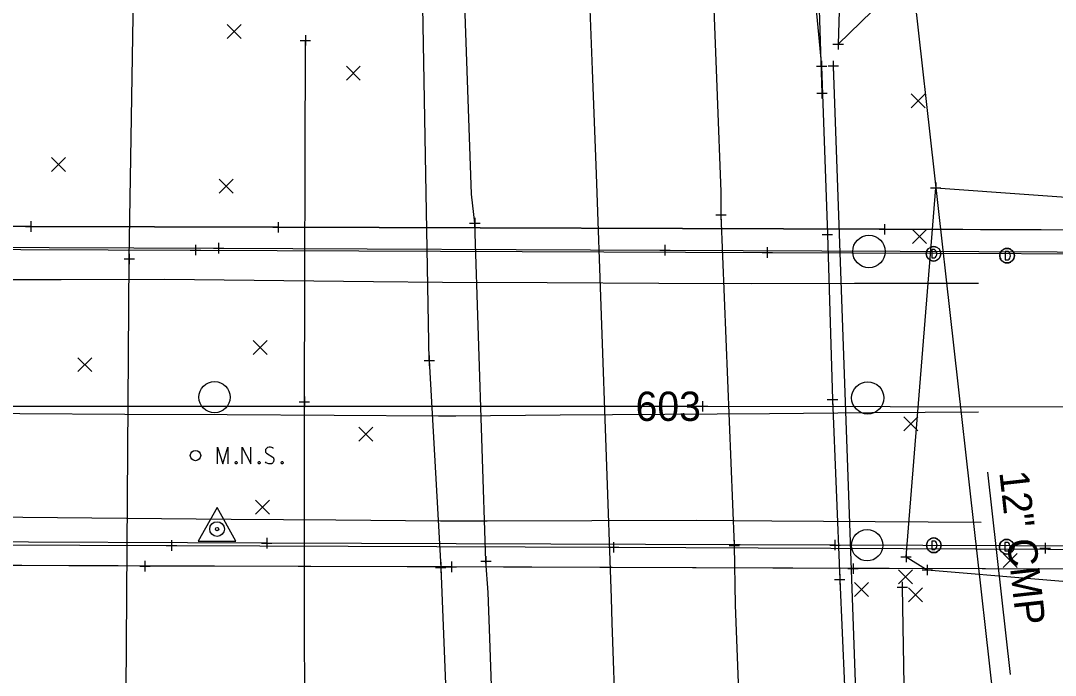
# Model space of a CAD drawing. Extents: x 146022 to 147632, y 437624 to 440659.
# Drawn here: x 146968.6 to 147067.5, y 438601.8 to 438664.4 of the extents above; entities that cross this region are included whole.
import ezdxf

# ---------------------------------------------------------------- set-up
doc = ezdxf.new("R2010")
doc.units = 0
for name, color, linetype in [('_CIVIL_CONSTRUCTION', 7, 'Continuous'), ('BR_X_SV_Bottom_of_Beam', 7, 'Continuous'), ('BR_X_SV_Pier', 7, 'Continuous'), ('Default', 7, 'Continuous'), ('DR_Channel', 7, 'Continuous'), ('DR_P_Paved_Gutter', 7, 'Continuous'), ('DR_P_Underdrain', 7, 'Continuous'), ('DR_X_Cells', 7, 'Continuous'), ('DR_X_Storm_Sewer', 7, 'Continuous'), ('DR_X_Text', 7, 'Continuous'), ('DT_X_Triangles', 7, 'Continuous'), ('GE_P_Alignment_100_Cardinal_Points', 7, 'Continuous'), ('GE_P_Alignment_100_Stations', 7, 'Continuous'), ('PF_X_Ground_Line', 7, 'Continuous'), ('PV_P_Curb', 7, 'Continuous'), ('PV_P_Joint', 7, 'Continuous'), ('RD_P_Anchor_Assembly', 7, 'Continuous'), ('RD_P_Fence', 7, 'Continuous'), ('RD_P_GR_Lt_Replaced', 7, 'Continuous'), ('RW_P_Const_Limits', 7, 'Continuous'), ('SC_Scratch3', 7, 'Continuous'), ('SH_Text', 7, 'Continuous'), ('SV_X_Terrain_Boundary', 7, 'Continuous'), ('UT_X_Electric', 7, 'Continuous')]:
    doc.layers.add(name, color=color, linetype=linetype)

msp = doc.modelspace()

# ---------------------------------------------------------------- linework, layer by layer
at = {"layer": '_CIVIL_CONSTRUCTION'}
for p, q in [((146988.311, 438662.735), (146989.644, 438664.07)), ((146988.311, 438664.07), (146989.644, 438662.735)), ((146999.698, 438658.743), (147001.031, 438660.078)), ((146999.698, 438660.078), (147001.031, 438658.743)), ((147053.702, 438656.103), (147055.036, 438657.438)), ((147053.702, 438657.438), (147055.036, 438656.103)), ((146971.505, 438650.019), (146972.838, 438651.354)), ((146971.505, 438651.354), (146972.838, 438650.019)), ((146987.528, 438647.937), (146988.861, 438649.272)), ((146987.528, 438649.272), (146988.861, 438647.937)), ((147053.825, 438643.128), (147055.158, 438644.463)), ((147053.825, 438644.463), (147055.158, 438643.128)), ((146990.785, 438632.502), (146992.118, 438633.837)), ((146990.785, 438633.837), (146992.118, 438632.502)), ((146974.032, 438630.864), (146975.365, 438632.199)), ((146974.032, 438632.199), (146975.365, 438630.864)), ((147052.986, 438625.203), (147054.319, 438626.538)), ((147052.986, 438626.538), (147054.319, 438625.203)), ((147000.881, 438624.21), (147002.214, 438625.545)), ((147000.881, 438625.545), (147002.214, 438624.21)), ((146991.024, 438617.231), (146992.357, 438618.566)), ((146991.024, 438618.566), (146992.357, 438617.231)), ((147062.501, 438612.127), (147063.834, 438613.462)), ((147062.501, 438613.462), (147063.834, 438612.127)), ((147052.474, 438610.572), (147053.807, 438611.907)), ((147052.474, 438611.907), (147053.807, 438610.572)), ((147048.271, 438609.372), (147049.605, 438610.707)), ((147048.271, 438610.707), (147049.605, 438609.372)), ((147053.453, 438608.838), (147054.787, 438610.173)), ((147053.453, 438610.173), (147054.787, 438608.838))]:
    msp.add_line(p, q, dxfattribs=at)
at = {"layer": 'BR_X_SV_Bottom_of_Beam'}
for points in [[(146915.587, 438639.808), (146925.317, 438639.819), (146934.821, 438639.83), (146945.2, 438639.842), (146955.198, 438639.747), (146962.426, 438639.678), (146972.429, 438639.685), (146982.304, 438639.693), (147002.305, 438639.484), (147008.894, 438639.416), (147018.894, 438639.375), (147029.574, 438639.335), (147038.394, 438639.296), (147048.275, 438639.31), (147058.405, 438639.324), (147060.13, 438639.326)], [(147060.147, 438626.995), (147049.92, 438626.917), (147040.15, 438626.842), (147030.152, 438626.766), (147020.152, 438626.69), (147010.154, 438626.614), (147008.517, 438626.602), (146998.516, 438626.658), (146988.288, 438626.717), (146978.515, 438626.772), (146968.486, 438626.829), (146964.186, 438626.853), (146953.877, 438626.667), (146944.082, 438626.48), (146934.171, 438626.293), (146931.304, 438626.257), (146922.277, 438626.712), (146912.643, 438627.012)], [(147060.393, 438616.42), (147050.239, 438616.494), (147040.369, 438616.566), (147033.157, 438616.619), (147023.159, 438616.592), (147013.16, 438616.565), (147008.681, 438616.553), (146998.682, 438616.645), (146988.669, 438616.737), (146978.685, 438616.83), (146968.751, 438616.922), (146966.697, 438616.94), (146956.246, 438616.918), (146946.661, 438616.897), (146936.054, 438616.876), (146930.378, 438616.865), (146921.088, 438616.438), (146911.185, 438616.183)]]:
    msp.add_lwpolyline(points, dxfattribs=at)
at = {"layer": 'BR_X_SV_Pier'}
for centre, radius in [((147049.66, 438642.354), 1.554), ((146987.091, 438628.418), 1.492), ((147049.538, 438628.346), 1.535), ((147049.487, 438614.263), 1.503)]:
    msp.add_circle(centre, radius, dxfattribs=at)
at = {"layer": 'DR_Channel'}
for points in [[(147043.412, 438708.595), (147044.478, 438678.513), (147045.162, 438657.493)], [(146993.311, 438472.759), (146995.719, 438578.194), (146995.684, 438627.981), (146995.782, 438662.545)]]:
    msp.add_lwpolyline(points, dxfattribs=at)
at = {"layer": 'DR_P_Paved_Gutter'}
msp.add_lwpolyline([(146978.603, 438595.669), (146978.94, 438641.642), (146979.937, 438703.502), (146984.388, 438761.316), (146986.686, 438784.307)], dxfattribs=at)
at = {"layer": 'DR_P_Underdrain'}
msp.add_lwpolyline([(147046.249, 438660.096), (147048.499, 438596.716)], dxfattribs=at)
at = {"layer": 'DR_X_Cells'}
for points in [[(147053.205, 438613.153), (147056.046, 438648.453), (147083.169, 438646.508), (147085.148, 438646.666)], [(147053.205, 438613.153), (147055.234, 438611.895), (147087.267, 438609.219), (147085.148, 438646.666)]]:
    msp.add_lwpolyline(points, dxfattribs=at)
at = {"layer": 'DR_X_Storm_Sewer'}
msp.add_line((147053.412, 438671.931), (147066.551, 438554.767), dxfattribs=at)
at = {"layer": 'DR_X_Text'}
msp.add_line((147063.177, 438601.899), (147061.008, 438621.247), dxfattribs=at)
at = {"layer": 'DT_X_Triangles'}
for p, q in [((147055.837, 438642.139), (147055.837, 438642.139)), ((147055.837, 438642.139), (147055.837, 438642.139)), ((147055.837, 438642.139), (147055.837, 438642.139)), ((147055.837, 438642.139), (147055.837, 438642.139)), ((147055.837, 438642.139), (147055.837, 438642.139)), ((147062.858, 438641.955), (147062.858, 438641.955)), ((147062.858, 438641.955), (147062.858, 438641.955)), ((147062.858, 438641.955), (147062.858, 438641.955)), ((147062.858, 438641.955), (147062.858, 438641.955)), ((147062.858, 438641.955), (147062.858, 438641.955)), ((147055.857, 438614.257), (147055.857, 438614.257)), ((147055.857, 438614.257), (147055.857, 438614.257)), ((147055.857, 438614.257), (147055.857, 438614.257)), ((147055.857, 438614.257), (147055.857, 438614.257)), ((147055.857, 438614.257), (147055.857, 438614.257)), ((147062.827, 438614.123), (147062.827, 438614.123)), ((147062.827, 438614.123), (147062.827, 438614.123)), ((147062.827, 438614.123), (147062.827, 438614.123)), ((147062.827, 438614.123), (147062.827, 438614.123)), ((147062.827, 438614.123), (147062.827, 438614.123))]:
    msp.add_line(p, q, dxfattribs=at)
for centre in [(147055.837, 438642.139), (147062.858, 438641.955), (147055.857, 438614.257), (147062.827, 438614.123)]:
    msp.add_circle(centre, 0.7, dxfattribs=at)
at = {"layer": 'GE_P_Alignment_100_Cardinal_Points'}
for points in [[(146886.697, 438643.146), (146914.629, 438642.971), (146987.485, 438642.673), (147030.154, 438642.484), (147082.653, 438642.27), (147087.676, 438642.282), (147088.142, 438642.428), (147088.538, 438642.44)], [(146886.273, 438614.58), (146893.974, 438614.564), (146939.097, 438614.385), (146982.973, 438614.237), (147025.25, 438614.063), (147087.547, 438613.803), (147088.31, 438613.791)]]:
    msp.add_lwpolyline(points, dxfattribs=at)
at = {"layer": 'GE_P_Alignment_100_Stations'}
for points in [[(146886.617, 438645.057), (146916.632, 438644.953), (146969.533, 438644.744), (146993.171, 438644.674), (147051.149, 438644.479), (147087.815, 438644.354), (147088.055, 438644.306), (147088.543, 438644.321)], [(147088.417, 438611.938), (147085.161, 438611.927), (147048.137, 438612.028), (147009.735, 438612.191), (146980.437, 438612.254), (146944.113, 438612.41), (146906.055, 438612.508), (146890.588, 438612.592), (146885.707, 438612.644)]]:
    msp.add_lwpolyline(points, dxfattribs=at)
at = {"layer": 'PF_X_Ground_Line'}
msp.add_lwpolyline([(147031.265, 439100.493), (147033.124, 439049.689), (147035.536, 438989.571), (147036.948, 438926.083), (147039.28, 438864.722), (147041.137, 438801.73), (147042.54, 438743.359), (147043.212, 438709.888), (147047.269, 438680.177), (147046.71, 438662.178), (147051.053, 438666.422), (147056.824, 438665.984), (147058.213, 438672.792), (147056.903, 438679.132), (147056.31, 438685.267)], dxfattribs=at)
at = {"layer": 'PV_P_Curb'}
msp.add_line((147025.042, 438609.21), (147023.6, 438649.734), dxfattribs=at)
for points in [[(147023.6, 438649.734), (147023.222, 438659.727), (147022.845, 438669.72), (147022.467, 438679.713), (147022.09, 438689.706), (147021.712, 438699.699), (147021.334, 438709.691), (147020.957, 438719.684), (147020.579, 438729.677), (147020.202, 438739.67), (147019.824, 438749.663), (147019.447, 438759.656), (147019.069, 438769.649), (147018.692, 438779.642), (147018.314, 438789.634), (147017.936, 438799.627), (147017.559, 438809.62), (147017.181, 438819.613), (147016.804, 438829.606), (147016.426, 438839.599), (147016.049, 438849.592), (147015.671, 438859.584)], [(146887.294, 438628.027), (146961.353, 438627.571), (147033.742, 438627.551), (147087.577, 438627.48)], [(147030.271, 438456.925), (147029.928, 438466.919), (147029.584, 438476.913), (147029.241, 438486.907), (147028.898, 438496.901), (147028.555, 438506.896), (147028.212, 438516.89), (147027.869, 438526.884), (147027.525, 438536.878), (147027.182, 438546.872), (147026.839, 438556.866), (147026.496, 438566.86), (147026.153, 438576.854), (147025.809, 438586.848), (147025.466, 438596.843), (147025.123, 438606.837), (147025.042, 438609.21)]]:
    msp.add_lwpolyline(points, dxfattribs=at)
at = {"layer": 'PV_P_Joint'}
msp.add_lwpolyline([(146985.529, 438614.654), (146989.129, 438614.654), (146987.329, 438617.874)], close=True, dxfattribs=at)
for radius in [0.7, 0.16]:
    msp.add_circle((146987.329, 438615.81), radius, dxfattribs=at)
at = {"layer": 'RD_P_Anchor_Assembly'}
for p, q in [((146995.282, 438662.545), (146996.282, 438662.545)), ((146995.782, 438663.045), (146995.782, 438662.045)), ((146995.782, 438662.545), (146995.782, 438662.545)), ((147046.71, 438662.678), (147046.71, 438661.678)), ((147046.21, 438662.178), (147047.21, 438662.178)), ((147046.71, 438662.178), (147046.71, 438662.178)), ((147045.134, 438660.585), (147045.134, 438659.585)), ((147046.249, 438660.596), (147046.249, 438659.596)), ((147044.634, 438660.085), (147045.634, 438660.085)), ((147045.134, 438660.085), (147045.134, 438660.085)), ((147045.749, 438660.096), (147046.749, 438660.096)), ((147046.249, 438660.096), (147046.249, 438660.096)), ((147044.662, 438657.493), (147045.662, 438657.493)), ((147045.162, 438657.993), (147045.162, 438656.993)), ((147045.162, 438657.493), (147045.162, 438657.493)), ((147055.546, 438648.453), (147056.546, 438648.453)), ((147056.046, 438648.953), (147056.046, 438647.953)), ((147056.046, 438648.453), (147056.046, 438648.453)), ((147011.976, 438645.558), (147011.976, 438644.558)), ((147035.004, 438645.875), (147036.004, 438645.875)), ((147035.504, 438646.375), (147035.504, 438645.375)), ((147035.504, 438645.875), (147035.504, 438645.875)), ((146969.033, 438644.744), (146970.033, 438644.744)), ((146969.533, 438645.244), (146969.533, 438644.244)), ((146969.533, 438644.744), (146969.533, 438644.744)), ((146992.671, 438644.674), (146993.671, 438644.674)), ((146993.171, 438645.174), (146993.171, 438644.174)), ((146993.171, 438644.674), (146993.171, 438644.674)), ((147011.476, 438645.058), (147012.476, 438645.058)), ((147011.976, 438645.058), (147011.976, 438645.058)), ((147045.684, 438644.484), (147045.684, 438643.484)), ((147050.649, 438644.479), (147051.649, 438644.479)), ((147051.149, 438644.979), (147051.149, 438643.979)), ((147051.149, 438644.479), (147051.149, 438644.479)), ((147045.184, 438643.984), (147046.184, 438643.984)), ((147045.684, 438643.984), (147045.684, 438643.984)), ((146984.777, 438642.496), (146985.777, 438642.496)), ((146985.277, 438642.996), (146985.277, 438641.996)), ((146985.277, 438642.496), (146985.277, 438642.496)), ((146986.985, 438642.673), (146987.985, 438642.673)), ((146987.485, 438643.173), (146987.485, 438642.173)), ((146987.485, 438642.673), (146987.485, 438642.673)), ((147029.654, 438642.484), (147030.654, 438642.484)), ((147030.154, 438642.984), (147030.154, 438641.984)), ((147030.154, 438642.484), (147030.154, 438642.484)), ((147039.933, 438642.754), (147039.933, 438641.754)), ((146978.44, 438641.642), (146979.44, 438641.642)), ((146978.94, 438642.142), (146978.94, 438641.142)), ((146978.94, 438641.642), (146978.94, 438641.642)), ((147039.433, 438642.254), (147040.433, 438642.254)), ((147039.933, 438642.254), (147039.933, 438642.254)), ((147007.124, 438631.915), (147008.124, 438631.915)), ((147007.624, 438632.415), (147007.624, 438631.415)), ((147007.624, 438631.915), (147007.624, 438631.915)), ((147046.174, 438628.711), (147046.174, 438627.711)), ((146995.184, 438627.981), (146996.184, 438627.981)), ((146995.684, 438628.481), (146995.684, 438627.481)), ((146995.684, 438627.981), (146995.684, 438627.981)), ((147033.742, 438628.051), (147033.742, 438627.051)), ((147045.674, 438628.211), (147046.674, 438628.211)), ((147046.174, 438628.211), (147046.174, 438628.211)), ((147033.242, 438627.551), (147034.242, 438627.551)), ((147033.742, 438627.551), (147033.742, 438627.551)), ((146982.973, 438614.737), (146982.973, 438613.737)), ((146992.08, 438614.964), (146992.08, 438613.964)), ((147036.778, 438614.744), (147036.778, 438613.744)), ((147046.407, 438614.779), (147046.407, 438613.779)), ((146982.473, 438614.237), (146983.473, 438614.237)), ((146982.973, 438614.237), (146982.973, 438614.237)), ((146991.58, 438614.464), (146992.58, 438614.464)), ((146992.08, 438614.464), (146992.08, 438614.464)), ((147024.75, 438614.063), (147025.75, 438614.063)), ((147025.25, 438614.563), (147025.25, 438613.563)), ((147025.25, 438614.063), (147025.25, 438614.063)), ((147036.278, 438614.244), (147037.278, 438614.244)), ((147036.778, 438614.244), (147036.778, 438614.244)), ((147045.907, 438614.279), (147046.907, 438614.279)), ((147046.407, 438614.279), (147046.407, 438614.279)), ((147066.008, 438613.978), (147067.008, 438613.978)), ((147066.508, 438614.478), (147066.508, 438613.478)), ((147066.508, 438613.978), (147066.508, 438613.978)), ((146980.437, 438612.754), (146980.437, 438611.754)), ((147013.041, 438613.231), (147013.041, 438612.231)), ((147052.705, 438613.153), (147053.705, 438613.153)), ((147053.205, 438613.653), (147053.205, 438612.653)), ((147053.205, 438613.153), (147053.205, 438613.153)), ((146979.937, 438612.254), (146980.937, 438612.254)), ((146980.437, 438612.254), (146980.437, 438612.254)), ((147008.213, 438612.13), (147009.213, 438612.13)), ((147008.713, 438612.63), (147008.713, 438611.63)), ((147008.713, 438612.13), (147008.713, 438612.13)), ((147009.235, 438612.191), (147010.235, 438612.191)), ((147009.735, 438612.691), (147009.735, 438611.691)), ((147009.735, 438612.191), (147009.735, 438612.191)), ((147012.541, 438612.731), (147013.541, 438612.731)), ((147013.041, 438612.731), (147013.041, 438612.731)), ((147047.637, 438612.028), (147048.637, 438612.028)), ((147048.137, 438612.528), (147048.137, 438611.528)), ((147048.137, 438612.028), (147048.137, 438612.028)), ((147054.734, 438611.895), (147055.734, 438611.895)), ((147055.234, 438612.395), (147055.234, 438611.395)), ((147055.234, 438611.895), (147055.234, 438611.895)), ((147046.368, 438610.995), (147047.368, 438610.995)), ((147046.868, 438611.495), (147046.868, 438610.495)), ((147046.868, 438610.995), (147046.868, 438610.995)), ((147052.345, 438610.265), (147053.345, 438610.265)), ((147052.845, 438610.765), (147052.845, 438609.765)), ((147052.845, 438610.265), (147052.845, 438610.265))]:
    msp.add_line(p, q, dxfattribs=at)
at = {"layer": 'RD_P_Fence'}
msp.add_lwpolyline([(147052.845, 438610.265), (147053.024, 438598.999), (147056.407, 438577.47), (147060.095, 438566.361), (147063.255, 438556.856), (147064.735, 438553.438)], dxfattribs=at)
at = {"layer": 'RD_P_GR_Lt_Replaced'}
for points in [[(147007.624, 438631.915), (147006.832, 438674.725), (147005.435, 438733.475), (147003.268, 438784.298), (147000.579, 438849.422), (146998.523, 438912.12), (146996.336, 438976.527), (146994.653, 439039.1), (146992.525, 439098.481), (146992.611, 439099.809)], [(147028.78, 439100.289), (147030.702, 439050.099), (147032.83, 438989.568), (147034.209, 438926.711), (147035.765, 438865.146), (147038.939, 438801.428), (147040.729, 438744.008), (147041.91, 438709.752), (147043.365, 438678.613), (147045.134, 438660.085), (147045.684, 438643.984), (147046.174, 438628.211), (147046.868, 438610.995), (147047.321, 438600.784)], [(147007.624, 438631.915), (147008.713, 438612.13), (147011.847, 438534.062)]]:
    msp.add_lwpolyline(points, dxfattribs=at)
at = {"layer": 'RW_P_Const_Limits'}
for points in [[(146987.363, 438622.04), (146987.363, 438623.64), (146987.87, 438622.04), (146988.355, 438623.64), (146988.355, 438622.04)], [(146989.733, 438622.04), (146989.733, 438623.64), (146990.56, 438622.04), (146990.56, 438623.64)], [(146992.709, 438623.527), (146992.687, 438623.552), (146992.654, 438623.577), (146992.555, 438623.615), (146992.434, 438623.64), (146992.345, 438623.64), (146992.312, 438623.64), (146992.169, 438623.602), (146992.048, 438623.527), (146991.971, 438623.426), (146991.949, 438623.325), (146991.949, 438623.249), (146991.971, 438623.149), (146992.059, 438623.061), (146992.665, 438622.683), (146992.72, 438622.632), (146992.742, 438622.582), (146992.764, 438622.506), (146992.764, 438622.431), (146992.753, 438622.355), (146992.742, 438622.305), (146992.72, 438622.242), (146992.698, 438622.191), (146992.676, 438622.154), (146992.643, 438622.116), (146992.61, 438622.091), (146992.566, 438622.065), (146992.533, 438622.053), (146992.434, 438622.04), (146992.279, 438622.04), (146992.18, 438622.065), (146992.037, 438622.154), (146991.949, 438622.229)], [(146989.127, 438622.254), (146989.182, 438622.254), (146989.215, 438622.229), (146989.248, 438622.179), (146989.248, 438622.116), (146989.215, 438622.065), (146989.182, 438622.04), (146989.127, 438622.04), (146989.094, 438622.065), (146989.061, 438622.116), (146989.061, 438622.179), (146989.094, 438622.229), (146989.127, 438622.254)], [(146991.342, 438622.254), (146991.397, 438622.254), (146991.431, 438622.229), (146991.464, 438622.179), (146991.464, 438622.116), (146991.431, 438622.065), (146991.397, 438622.04), (146991.342, 438622.04), (146991.309, 438622.065), (146991.276, 438622.116), (146991.276, 438622.179), (146991.309, 438622.229), (146991.342, 438622.254)], [(146993.525, 438622.254), (146993.58, 438622.254), (146993.613, 438622.229), (146993.646, 438622.179), (146993.646, 438622.116), (146993.613, 438622.065), (146993.58, 438622.04), (146993.525, 438622.04), (146993.492, 438622.065), (146993.459, 438622.116), (146993.459, 438622.179), (146993.492, 438622.229), (146993.525, 438622.254)]]:
    msp.add_lwpolyline(points, dxfattribs=at)
msp.add_circle((146985.273, 438622.84), 0.497, dxfattribs=at)
at = {"layer": 'SC_Scratch3'}
for points in [[(147011.665, 438647.832), (147011.304, 438657.825), (147010.943, 438667.819), (147010.582, 438677.812), (147010.221, 438687.806), (147009.86, 438697.799), (147009.499, 438707.793), (147009.139, 438717.786), (147008.778, 438727.78), (147008.417, 438737.773), (147008.056, 438747.767), (147007.695, 438757.76), (147007.334, 438767.754), (147006.973, 438777.747), (147006.612, 438787.741), (147006.251, 438797.734), (147005.89, 438807.728), (147005.529, 438817.721), (147005.169, 438827.715), (147004.808, 438837.708), (147004.447, 438847.702), (147004.086, 438857.695), (147003.725, 438867.689)], [(147027.903, 438858.713), (147028.253, 438848.719), (147028.336, 438846.326), (147028.695, 438836.333), (147029.054, 438826.339), (147029.413, 438816.345), (147029.772, 438806.352), (147030.131, 438796.358), (147030.49, 438786.365), (147030.849, 438776.371), (147031.208, 438766.378), (147031.567, 438756.384), (147031.926, 438746.391), (147032.285, 438736.397), (147032.644, 438726.403), (147033.003, 438716.41), (147033.362, 438706.416), (147033.721, 438696.423), (147034.08, 438686.429), (147034.439, 438676.436), (147034.769, 438667.24), (147035.152, 438657.247), (147035.503, 438648.06)], [(147013.256, 438609.731), (147013.041, 438612.731), (147011.976, 438645.058), (147011.665, 438647.832)], [(147035.503, 438648.06), (147035.504, 438645.875), (147036.778, 438614.244), (147036.865, 438608.561)], [(147018.395, 438463.587), (147018.059, 438473.582), (147017.722, 438483.576), (147017.386, 438493.57), (147017.05, 438503.564), (147016.713, 438513.56), (147016.651, 438515.422), (147016.291, 438525.416), (147015.931, 438535.409), (147015.571, 438545.403), (147015.212, 438555.397), (147014.852, 438565.39), (147014.492, 438575.384), (147014.132, 438585.377), (147013.772, 438595.371), (147013.413, 438605.365), (147013.256, 438609.731)], [(147036.865, 438608.561), (147037.241, 438598.568), (147037.618, 438588.575), (147037.995, 438578.582), (147038.372, 438568.589), (147038.749, 438558.596), (147039.125, 438548.603), (147039.365, 438542.249), (147039.716, 438532.255), (147040.068, 438522.261), (147040.419, 438512.268), (147040.77, 438502.274), (147041.122, 438492.28), (147041.473, 438482.286), (147041.824, 438472.292), (147042.176, 438462.298)]]:
    msp.add_lwpolyline(points, dxfattribs=at)
at = {"layer": 'SH_Text'}
msp.add_lwpolyline([(146885.966, 438642.868), (146926.812, 438642.691), (146985.277, 438642.496), (147039.933, 438642.254), (147088.536, 438642.067), (147088.54, 438627.583), (147088.397, 438614.111), (147046.407, 438614.279), (146992.08, 438614.464), (146931.328, 438614.71), (146885.67, 438614.858), (146885.649, 438627.845)], close=True, dxfattribs=at)
at = {"layer": 'SV_X_Terrain_Boundary'}
msp.add_lwpolyline([(146885.67, 438614.858), (146885.705, 438612.644), (147088.417, 438611.938), (147088.276, 438614.389), (147088.54, 438627.583), (147088.536, 438642.067), (147088.543, 438644.321), (147051.149, 438644.479), (146993.171, 438644.674), (146969.533, 438644.744), (146886.231, 438645.023), (146885.966, 438642.868), (146885.966, 438642.868), (146885.649, 438627.845)], close=True, dxfattribs=at)
at = {"layer": 'UT_X_Electric'}
for points in [[(147055.937, 438642.539), (147055.657, 438642.539), (147055.657, 438641.739), (147055.937, 438641.739)], [(147062.958, 438642.355), (147062.678, 438642.355), (147062.678, 438641.555), (147062.958, 438641.555)], [(147055.957, 438614.657), (147055.677, 438614.657), (147055.677, 438613.857), (147055.957, 438613.857)], [(147062.927, 438614.524), (147062.647, 438614.524), (147062.647, 438613.724), (147062.927, 438613.724)]]:
    msp.add_lwpolyline(points, dxfattribs=at)
for centre, radius, start, end in [((147055.837, 438642.139), 0.7, 150.01836, 209.98164), ((147055.837, 438642.139), 0.7, 60.01836, 120.01574), ((147055.682, 438642.138), 0.474, 302.51483, 57.48517), ((147055.837, 438642.139), 0.7, 330.01836, 29.98164), ((147062.858, 438641.955), 0.7, 60.01836, 120.01574), ((147055.837, 438642.139), 0.7, 239.98426, 299.98164), ((147062.858, 438641.955), 0.7, 150.01836, 209.98164), ((147062.703, 438641.955), 0.474, 302.51483, 57.48517), ((147062.858, 438641.955), 0.7, 330.01836, 29.98164), ((147062.858, 438641.955), 0.7, 239.98426, 299.98164), ((147055.857, 438614.257), 0.7, 60.01836, 120.01574), ((147062.827, 438614.123), 0.7, 60.01836, 120.01574), ((147055.857, 438614.257), 0.7, 150.01836, 209.98164), ((147055.702, 438614.257), 0.474, 302.51483, 57.48517), ((147055.857, 438614.257), 0.7, 330.01836, 29.98164), ((147062.827, 438614.123), 0.7, 150.01836, 209.98164), ((147062.672, 438614.123), 0.474, 302.51483, 57.48517), ((147062.827, 438614.123), 0.7, 330.01836, 29.98164), ((147055.857, 438614.257), 0.7, 239.98426, 299.98164), ((147062.827, 438614.123), 0.7, 239.98426, 299.98164)]:
    msp.add_arc(centre, radius, start, end, dxfattribs=at)

# ---------------------------------------------------------------- texts
at = {"layer": 'Default'}
msp.add_text('603', height=2.8, dxfattribs=at).set_placement((147027.345, 438626.151))
at = {"layer": 'DR_X_Text'}
msp.add_text('12" CMP', height=2.8, rotation=276.39843, dxfattribs=at).set_placement((147062.115, 438621.256))

doc.saveas('drawing.dxf')
